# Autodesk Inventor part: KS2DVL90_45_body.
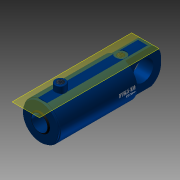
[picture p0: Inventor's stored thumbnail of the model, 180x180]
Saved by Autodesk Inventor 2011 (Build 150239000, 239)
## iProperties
Created: 2010-10
Document SubType Name: Modeling
Designer: TB
Mass: 405.061 g
Surface Area: 916.939 cm^2
Volume: 405.061 cm^3
Density: 1 g/cm^3
Author: TB
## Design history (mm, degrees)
sketch "Sketch2"
  geometry: L1 (-35, -3)-(-35, 3); L2 (-35, -9)-(-35, 9); L3 (-35, 0)-(-35, 52.5); L4 (-35, 52.5)-(-249, 52.5); L5 (-249, 52.5)-(-249, 50); L6 (-249, 50)-(-254, 50); L7 (-254, 50)-(-254, 26.5); L8 (-254, 26.5)-(-257, 23.5); L9 (-257, 23.5)-(-257, 22.5); L10 (-257, 22.5)-(-194, 22.5); L11 (-194, 22.5)-(-194, 45); L12 (-194, 45)-(-55, 45); L13 (-55, 45)-(-55, 0); L14 (-55, 0)-(-35, 0); L15 (-55, 0)-(-148.421, 0); L16 (-35, 9)-(-32, 12) reference; L17 (-32, 12)-(-35, 12) reference; L18 (-35, 12)-(-35, 9) reference; L19 (-32, 12)-(-35, 9) reference; L20 (-32, 12)-(-35, 12) reference; L21 (-35, 9)-(-35, 12) reference; L22 (-35, 9)-(-32, 12) reference; 1 further point
  constraints: 44 end point, 8 perpendicular, 6 parallel, 5 collinear, 2 horizontal, 2 vertical, 1 coincident, 1 midpoint, 1 point on line, 10 other
  dimensions: "DiaY" = 105 diameter of L4 L15; "DiaI" = 90 diameter of L12 L15; "d4" = 1 distance of L8.end L9.end; "d5" = 45 deg angle of L10 L8; "d6" = 3 distance between parallel lines of L7 L9; "DiaStang" = 45 diameter of L10 L15; "RindDia" = 100 diameter of L6 L15; "RingLengde" = 5 distance of L5.end L6.end; "RingTykk" = 60 distance between parallel lines of L11 L7; "KroppLengde" = 219 distance between parallel lines of L7 L3 (derived); "BunnTykkelse" = 20 distance between parallel lines of L13 L3
revolve "Kropp" sketch "Sketch2" stored, may be unused: angle "d13" = 90 deg
sketch "Sketch3"
  geometry: L1 (-55, -45)-(-55, 45) reference; L2 (-55, 0.01)-(-155, 0.01); L3 (-155, -0.01)-(-55, -0.01); A1 r 0.01 centre (-155, 0) between (-155, 0.01) and (-155, -0.01); A2 r 0.01 centre (-55, 0) between (-55, -0.01) and (-55, 0.01); 2 further points
  constraints: 4 end point, 4 point on circle, 4 tangent, 2 centre point, 1 coincident, 1 midpoint, 1 parallel, 1 perpendicular
  dimensions: "d17" = 0.01 radius of A2; "d18" = 100 distance of L2.start L2.end (= Slaglengde)
feature "BaneTransitionalConstraint" sketch "Sketch3" dims "d19" = 2, "d20" = 0
sketch "Sketch6"
  geometry: L1 (-73.5, 0)-(73.5, 0) reference; L2 (12.46, 51)-(-11.843, 51); L3 (52.5, 0)-(52.5, 31.248); L4 (-52.5, 0)-(-52.5, -18.451); A1 r 52.5 centre (0, 0) between (-52.5, 0) and (52.5, 0) reference; 2 further points
  constraints: 6 end point, 2 point on circle, 2 vertical, 2 other
  dimensions: "d30" = 51 distance from line of point (0, 0) L2 (computed from DiaY); "d31" = 0 deg angle of L1 L2 (computed from Vinkel_Plussport); "d37" = 90 deg angle of L2 L3; "d38" = 90 deg angle of L2 L4
  node "Projected Loop3"
workplane "Work Plane5"
sketch "Sketch7"
  geometry: L1 (12.46, -308.4)-(12.46, 51.4) reference; L2 (-19.633, -35)-(38.367, -35) reference; C1 r 15 at (12.46, -52.5); 1 further point
  constraints: 1 centre point, 1 point on line
  dimensions: "PortDia" = 30 diameter of C1
extrude "Extrusion2" cut sketch "Sketch7" stored distance "d34" = 1.5; taper "d35" = 0 deg
workplane "Work Plane7"
sketch "Sketch4"
  geometry: L1 (-16.68, -40)-(-16.68, -78.777); L2 (-16.68, -78.777)-(16.68, -78.777); L3 (16.68, -78.777)-(16.68, -40); L4 (16.68, -40)-(-16.68, -40); L5 (-40.643, -40)-(0, -40); L6 (-29, -35)-(29, -35); L7 (0, -35)-(0, -40); 2 further points
  constraints: 6 end point, 2 midpoint, 2 other
  dimensions: "d40" = 5 distance of L7.start L5.end
emboss "Emboss1" sketch "Sketch4" dims "d4" = 1, "d5" = 45 deg, "d6" = 3, "d22" = 0.2, "d23" = 0, "DiaI" = 90, "DiaY" = 105, "RindDia" = 100, "DiaStang" = 45, "RingTykk" = 60, "RingLengde" = 5, "KroppLengde" = 219 (derived), "BunnTykkelse" = 20
workplane "Work Plane8"
sketch "Sketch8"
  geometry: L1 (-29, -35)-(29, -35); L2 (0, -35)-(0, -40); L3 (-5.906, -110.587)-(-5.906, -40); L4 (-5.906, -40)-(5.906, -40); L5 (5.906, -40)-(5.906, -110.587); L6 (5.906, -110.587)-(-5.906, -110.587); L7 (52.5, -35)-(-52.5, -35); L8 (52.5, -35)-(-52.5, -35) reference; 3 further points
  constraints: 6 end point, 4 midpoint, 2 other
  dimensions: "d42" = 5 distance of L2.start L2.end
emboss "Emboss2" sketch "Sketch8" dims "d4" = 1, "d5" = 45 deg, "d6" = 3, "d43" = 0.2, "d44" = 0, "DiaI" = 90, "DiaY" = 105, "RindDia" = 100, "DiaStang" = 45, "RingTykk" = 60, "RingLengde" = 5, "KroppLengde" = 219 (derived), "BunnTykkelse" = 20
sketch "Sketch9"
  geometry: A1 r 12.5 centre (9.367, -52.5) between (0, -60.776) and (18.735, -60.776) reference; 1 further point
hole "Hole1" sketch "Sketch9" at (9.367, -52.5) diameter "d45" = 14.95; stored, may be unused: countersink angle "d49" = 82 deg, drill point angle "d51" = 118 deg; dims "d46" = 6, "d47" = 3.023, "d48" = 2, "DiaInvPluss" = 15
workplane "Work Plane9"
sketch "Sketch10"
  geometry: L1 (-73.5, 0)-(73.5, 0) reference; L2 (0, 52.5)-(13.136, 52.5); L3 (0, 52.5)-(0, 31.79); L4 (15, 50.312)-(15, 70); L5 (15, 70)-(0, 70); L6 (0, 70)-(0, 52.5); L7 (0, 52.5)-(15, 50.312); C1 r 52.5 at (0, 0) reference; A1 r 52.5 centre (0, 0) between (0, 52.5) and (15, 50.312); 1 further point
  constraints: 12 end point, 4 perpendicular, 2 concentric, 2 point on circle, 1 centre point, 1 point on line, 1 tangent
  dimensions: "d53" = 0 deg angle of L1 L2 (computed from Vinkel_Minusport); "DiaUtvStussMinus" = 30 diameter of L4 L3; "HøydeStussMinuss" = 17.5 distance between parallel lines of L2 L5
revolve "Revolution2" sketch "Sketch10" stored, may be unused: angle "d56" = 90 deg
hole "Hole2" diameter "d59" = 18.631; stored, may be unused: countersink angle "d63" = 82 deg, drill point angle "d65" = 118 deg; dims "d57" = 10, "d58" = 10, "d60" = 6, "d61" = 3.023, "d62" = 2, "DiaInvStussMinus" = 18
fillet "Fillet1" dims "d66" = 2
sketch "Sketch15"
  geometry: L1 (19, -48.941)-(19, 48.941); L2 (-19, -48.941)-(-19, 48.941); L3 (0, 73.5)-(0, -73.5) reference; A1 r 52.5 centre (0, 0) between (19, -48.941) and (-19, -48.941) reference; A2 r 52.5 centre (0, 0) between (19, 48.941) and (-19, 48.941); A3 r 52.5 centre (0, 0) between (-19, -48.941) and (19, -48.941)
  constraints: 8 point on circle, 4 end point, 4 point on line, 2 centre point, 2 concentric, 2 parallel, 1 coincident
  dimensions: "EyeBunnTykk" = 19 distance from line of L1 A1.centre; "EyeBunnTykk2" = 19 distance from line of A1.centre L2
extrude "Extrusion6" join sketch "Sketch15" taper "d98" = 0 deg; distance "LengdeEyeMinussBunntykk" = 100
sketch "Sketch16"
  geometry: L1 (-249, 52.5)-(65, 52.5) reference; L2 (-249, -52.5)-(65, -52.5) reference; L3 (-249, 52.5)-(65, 52.5) reference; L4 (65, 52.5)-(65, 48.941) reference; L5 (65, -48.941)-(65, 48.941) reference; L6 (-308.843, 0)-(138.06, 0) reference; L7 (20.5, 52.5)-(65, 52.5); L8 (65, 52.5)-(65, 8); A1 r 44.5 centre (20.5, 8) between (65, 8) and (20.5, 52.5); 6 further points; 2 other entities
  constraints: 4 end point, 4 tangent, 2 point on circle, 2 point on line, 1 centre point, 1 collinear, 1 perpendicular, 2 other
  dimensions: "d137" = 8 distance from line of L8.end L6
extrude "Extrusion7" cut sketch "Sketch16" taper "d102" = 0 deg; stored distance "ExtruEyeBunn" = 38
mirror "Mirror1"
sketch "Sketch20"
  geometry: L1 (-249, 52.5)-(65, 52.5) reference; L2 (65, -48.941)-(65, 48.941) reference; L3 (65, 52.5)-(65, 48.941) reference; L4 (-308.008, 0)-(133.047, 0) reference; L5 (-35, -48.941)-(-35, 48.941) reference; L6 (-35, 0)-(11, 0); L7 (11, 0)-(11, 20.918); L8 (34.022, 49.669)-(28.1, 51.873); A1 r 30 centre (22, 22.5) between (28.1, 51.873) and (22, 52.5); A2 r 54.745 centre (11, 0) between (65, 9) and (34.022, 49.669); 1 further point
  constraints: 6 end point, 4 point on circle, 3 point on line, 2 centre point, 1 coincident, 1 midpoint, 1 perpendicular, 1 tangent
  dimensions: "d147" = 46 distance of L6.start L6.end; "d150" = 30 radius of A1; "d157" = 9 distance from line of L4 A2.start; "d158" = 20.4178 deg angle of L1 L8
extrude "Extrusion10" cut sketch "Sketch20" stored distance "d144" = 10; taper "d145" = 0 deg
mirror "Mirror2"
sketch "Sketch17"
  geometry: L1 (97.883, 0)-(0, 0) reference; L2 (48.941, -286.4)-(48.941, 164.4) reference; C1 r 28.5 at (48.941, 50); 1 further point
  constraints: 1 centre point, 1 point on line
  dimensions: "DiaHullEyeBunn" = 57 diameter of C1; "d125" = 50 distance from line of C1.centre L1
extrude "Extrusion8" cut sketch "Sketch17" taper "d105" = 0 deg; distance "ExtruHullEye" = 38
pattern_circular "Circular Pattern1 Only Subsea" dims "d108" = 180 deg (derived)
workplane "Work Plane11"
sketch "Sketch18"
  geometry: L1 (0, -66)-(0, 11) reference; L2 (45, -55)-(-45, -55) reference; L3 (45, -55)-(-45, -55) reference; C1 r 15 at (0, -29); 1 further point
  constraints: 1 centre point
  dimensions: "DiaForsenkPlussPort" = 30 diameter of C1; "PlassPlussport" = 26 distance from line of L2 C1.centre
extrude "Extrusion9" cut sketch "Sketch18" stored distance "d113" = 10; taper "d114" = 0 deg
sketch "Sketch19"
  geometry: 10 further points
  constraints: 1 other
hole "Hole3" sketch "Sketch19" at (0, -29) diameter "d115" = 18.631; stored, may be unused: countersink angle "d119" = 90 deg, drill point angle "d121" = 118 deg; dims "d116" = 6, "d117" = 4, "d118" = 2, "d120" = 14.5
pattern_circular "Circular Pattern2 Only Subsea" dims angle "d123" = 360 deg
body "Solid1"
chamfer "Chamfer" distance "Chamfer" = 1; stored, may be unused: second distance "d15" = 2, angle "d16" = 45 deg
node "Projected Loop2"
body "Srf1"
node "Projected Loop10"
other parameters: "Slaglengde" = 100, "Forlengelse_rør" = 0, "Vinkel_Plussport" = 0 [user parameter; used in 1 equation term], "Vinkel_Minusport" = 0, "d32" = 90 deg, "d39" = 90 deg, "d41" = 90 deg, "PortMinusPlass" = -56, "Minusport2" = 180 deg, "ForsenkningPlussPort" = 50.7 (derived)
